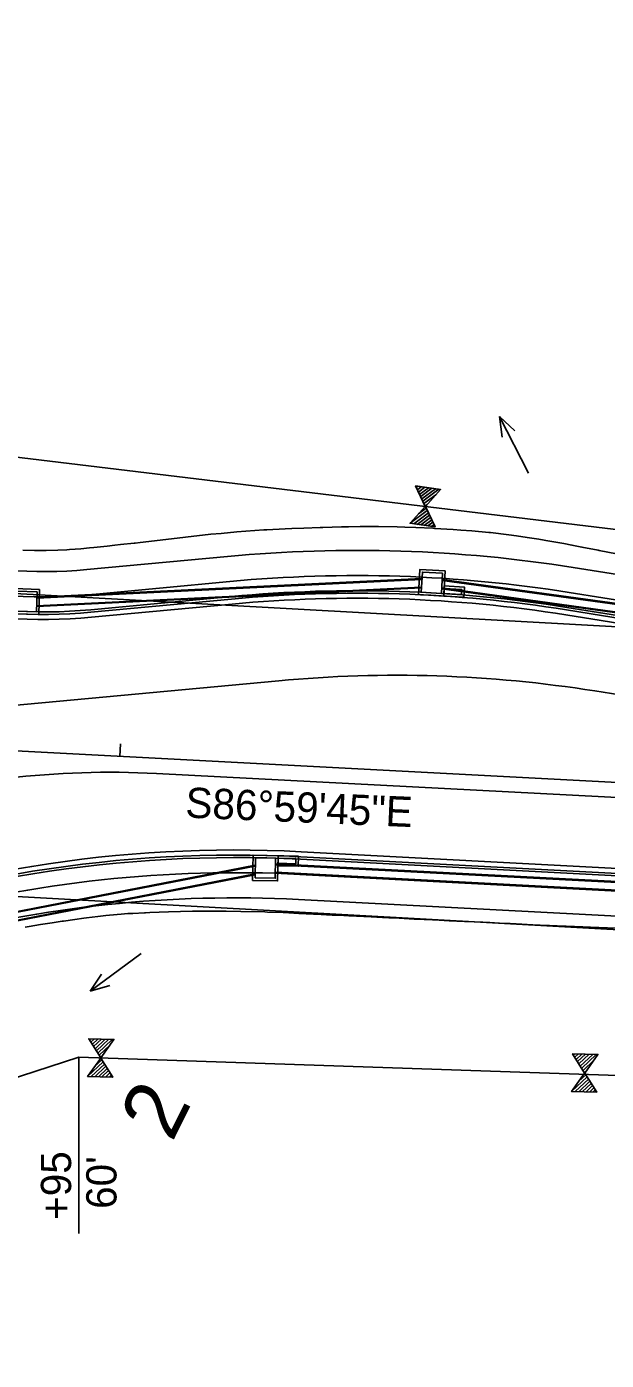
# Model space of a CAD drawing. Extents: x 670017 to 673226, y 705371 to 707498.
# Drawn here: x 671881.1 to 671996.1, y 706412.9 to 706677.4 of the extents above; entities that cross this region are included whole.
import ezdxf

# ---------------------------------------------------------------- set-up
doc = ezdxf.new("R2010")
doc.units = 0
for name, color, linetype in [('EL L 264', 7, 'Continuous'), ('EL R 264', 7, 'Continuous'), ('R_Drainage Flow Lines', 7, 'Continuous'), ('R_Drainage Stage 1', 7, 'Continuous'), ('R_Drainage Stage 2', 7, 'Continuous'), ('R_Fence', 7, 'Continuous'), ('R_Horz Alg', 7, 'Continuous'), ('R_Horz Alg Station', 7, 'Continuous'), ('R_Horz Alg Station Annot', 7, 'Continuous'), ('R_Horz Bearing', 7, 'Continuous'), ('R_No Plot', 7, 'Continuous'), ('R_No Plot FOC', 7, 'Continuous'), ('R_Proposed Const Limits', 7, 'Continuous'), ('R_Proposed Const Limits Stage 2', 7, 'Continuous'), ('R_Proposed Median', 7, 'Continuous'), ('R_Proposed Road', 7, 'Continuous'), ('R_Proposed Road Stage 2', 7, 'Continuous'), ('R_Proposed Sidewalk Stage 1', 7, 'Continuous'), ('R_Proposed Sidewalk Stage 2', 7, 'Continuous'), ('R_ROW', 7, 'Continuous'), ('R_ROW Annot', 7, 'Continuous'), ('R_Water Annot', 7, 'Continuous'), ('S_EXIST_ROW', 7, 'Continuous')]:
    doc.layers.add(name, color=color, linetype=linetype)

# ---------------------------------------------------------------- blocks, each defined once
blk = doc.blocks.new('FLOW ARROW')
at = {"layer": 'R_Water Annot'}
for p, q in [((-12.57, 0), (0, 0)), ((0, 0), (-3.85, 1.4)), ((0, 0), (-3.85, -1.4))]:
    blk.add_line(p, q, dxfattribs=at)

msp = doc.modelspace()

# ---------------------------------------------------------------- linework, layer by layer
at = {"layer": 'EL L 264'}
for p, q in [((671893.98, 706560.26), (671921.88, 706562.87)), ((671893.98, 706560.26), (671921.88, 706562.87)), ((671988.06, 706560.74), (672090.97, 706544.34)), ((671988.06, 706560.74), (672090.97, 706544.34))]:
    msp.add_line(p, q, dxfattribs=at)
for centre, radius, start, end in [((671884.56, 706660.82), 101, 237.03, 275.3546), ((671884.56, 706660.82), 101, 237.03, 275.3546), ((671946.51, 706300.03), 264, 80.9468, 95.3546), ((671946.51, 706300.03), 264, 80.9468, 95.3546)]:
    msp.add_arc(centre, radius, start, end, dxfattribs=at)
at = {"layer": 'EL R 264'}
msp.add_line((671935.55, 706513.76), (672188.31, 706500.5), dxfattribs=at)
msp.add_arc((671922.4, 706263.11), 251, 86.9958, 111.4581, dxfattribs=at)
at = {"layer": 'R_Drainage Stage 1'}
for p, q in [((671959.44, 706566.26), (671883.12, 706562.56)), ((671959.43, 706566.09), (671883.12, 706562.4)), ((671959.54, 706567.93), (671883.17, 706564.23)), ((671959.53, 706567.76), (671883.17, 706564.07)), ((672148.36, 706540.47), (671963.43, 706565.91)), ((672148.37, 706540.64), (671963.44, 706566.08)), ((672148.44, 706542.14), (671963.52, 706567.58)), ((672148.45, 706542.31), (671963.53, 706567.75))]:
    msp.add_line(p, q, dxfattribs=at)
for points in [[(671958.86, 706564.75), (671963.85, 706564.47), (671964.13, 706569.46), (671959.14, 706569.74)], [(671959.38, 706565.22), (671963.38, 706565), (671963.6, 706568.99), (671959.61, 706569.22)], [(671883.72, 706565.8), (671878.72, 706565.95), (671878.57, 706560.96), (671883.57, 706560.8)], [(671963.96, 706566.47), (671967.95, 706566.24), (671967.84, 706564.24), (671963.85, 706564.47)], [(671963.93, 706565.97), (671967.43, 706565.77), (671967.37, 706564.77), (671963.88, 706564.97)], [(671883.21, 706565.31), (671879.21, 706565.44), (671879.08, 706561.44), (671883.08, 706561.32)]]:
    msp.add_lwpolyline(points, close=True, dxfattribs=at)
at = {"layer": 'R_Drainage Stage 2'}
for p, q in [((671926.49, 706511.08), (671823.91, 706491.17)), ((671926.48, 706510.91), (671823.97, 706491.01)), ((672121.25, 706501.26), (671930.49, 706511.18)), ((672121.26, 706501.43), (671930.5, 706511.35)), ((671926.45, 706509.38), (671824.53, 706489.59)), ((671926.44, 706509.2), (671824.59, 706489.44)), ((672121.17, 706499.6), (671930.45, 706509.51)), ((672121.17, 706499.76), (671930.46, 706509.68))]:
    msp.add_line(p, q, dxfattribs=at)
for points in [[(671925.92, 706508.09), (671930.92, 706507.97), (671931.03, 706512.97), (671926.04, 706513.09)], [(671931.03, 706512.97), (671935.03, 706512.88), (671934.99, 706510.88), (671930.99, 706510.97)], [(671926.43, 706508.58), (671930.43, 706508.49), (671930.52, 706512.49), (671926.52, 706512.58)], [(671931.02, 706512.47), (671934.52, 706512.39), (671934.5, 706511.39), (671931, 706511.47)]]:
    msp.add_lwpolyline(points, close=True, dxfattribs=at)
at = {"layer": 'R_Fence'}
for p, q in [((671958.7, 706586.25), (671958.4, 706586.02)), ((671959.4, 706586.14), (671958.62, 706585.56)), ((671960.1, 706586.04), (671958.84, 706585.1)), ((671960.8, 706585.94), (671959.06, 706584.64)), ((671961.5, 706585.84), (671959.28, 706584.18)), ((671962.2, 706585.74), (671959.5, 706583.72)), ((671962.9, 706585.64), (671959.72, 706583.26)), ((671962.28, 706584.55), (671959.94, 706582.8)), ((671960.38, 706581.88), (671958.87, 706580.75)), ((671960.57, 706582.65), (671960.16, 706582.34)), ((671960.6, 706581.42), (671957.2, 706578.89)), ((671960.81, 706580.96), (671957.9, 706578.78)), ((671961.03, 706580.5), (671958.6, 706578.68)), ((671961.25, 706580.04), (671959.3, 706578.58)), ((671961.47, 706579.58), (671960, 706578.48)), ((671961.69, 706579.12), (671960.7, 706578.38)), ((671961.91, 706578.66), (671961.4, 706578.28)), ((671962.13, 706578.2), (671962.1, 706578.18)), ((671893.89, 706476.67), (671893.62, 706476.41)), ((671894.6, 706476.65), (671893.89, 706475.98)), ((671895.31, 706476.63), (671894.16, 706475.55)), ((671896.01, 706476.61), (671894.43, 706475.12)), ((671896.72, 706476.59), (671894.7, 706474.68)), ((671897.43, 706476.57), (671894.97, 706474.25)), ((671898.13, 706476.54), (671895.24, 706473.82)), ((671897.64, 706475.39), (671895.51, 706473.39)), ((671896.16, 706473.31), (671895.78, 706472.95)), ((671989.86, 706473.68), (671989.59, 706473.42)), ((671990.57, 706473.66), (671989.86, 706472.99)), ((671991.27, 706473.64), (671990.13, 706472.56)), ((671991.98, 706473.62), (671990.4, 706472.13)), ((671992.69, 706473.6), (671990.67, 706471.7)), ((671993.4, 706473.58), (671990.94, 706471.26)), ((671994.1, 706473.56), (671991.21, 706470.83)), ((671896.32, 706472.09), (671893.24, 706469.19)), ((671896.59, 706471.66), (671893.95, 706469.17)), ((671896.86, 706471.22), (671894.66, 706469.14)), ((671896.05, 706472.52), (671894.68, 706471.23)), ((671897.13, 706470.79), (671895.36, 706469.12)), ((671993.6, 706472.4), (671991.48, 706470.4)), ((671897.4, 706470.36), (671896.07, 706469.1)), ((671897.67, 706469.93), (671896.78, 706469.08)), ((671897.94, 706469.49), (671897.48, 706469.06)), ((671898.21, 706469.06), (671898.19, 706469.04)), ((671992.29, 706469.1), (671989.21, 706466.2)), ((671992.56, 706468.67), (671989.92, 706466.18)), ((671992.83, 706468.24), (671990.62, 706466.16)), ((671992.02, 706469.53), (671990.65, 706468.24)), ((671992.13, 706470.32), (671991.75, 706469.97)), ((671993.1, 706467.8), (671991.33, 706466.13)), ((671993.37, 706467.37), (671992.04, 706466.11)), ((671993.64, 706466.94), (671992.74, 706466.09)), ((671993.91, 706466.51), (671993.45, 706466.07)), ((671994.18, 706466.07), (671994.16, 706466.05))]:
    msp.add_line(p, q, dxfattribs=at)
for points in [[(671960.21, 706582.23), (671960.21, 706582.25), (671963.22, 706585.59), (671958.27, 706586.31), (671960.2, 706582.25), (671960.2, 706582.23), (671957.19, 706578.89), (671962.14, 706578.17), (671960.21, 706582.23)], [(671895.85, 706472.85), (671895.85, 706472.87), (671898.45, 706476.53), (671893.45, 706476.68), (671895.84, 706472.87), (671895.84, 706472.85), (671893.23, 706469.19), (671898.23, 706469.04), (671895.85, 706472.85)], [(671991.81, 706469.86), (671991.81, 706469.88), (671994.42, 706473.55), (671989.42, 706473.69), (671991.8, 706469.88), (671991.8, 706469.87), (671989.2, 706466.2), (671994.2, 706466.05), (671991.81, 706469.86)]]:
    msp.add_lwpolyline(points, dxfattribs=at)
at = {"layer": 'R_Horz Alg'}
msp.add_line((670501.52, 706606.05), (672734.79, 706488.84), dxfattribs=at)
at = {"layer": 'R_Horz Alg Station'}
msp.add_lwpolyline([(671899.73, 706535.17), (671899.6, 706532.67)], dxfattribs=at)
at = {"layer": 'R_No Plot'}
msp.add_lwpolyline([(672600.73, 706535.93), (672600.73, 706535.93), (672146.36, 706559.78), (671852.81, 706595.21), (671791.92, 706679.49), (671797.39, 707089.58)], dxfattribs=at)
at = {"layer": 'R_No Plot FOC'}
for p, q in [((671893.89, 706561.25), (671921.78, 706563.87)), ((672091.13, 706545.33), (671988.21, 706561.72)), ((672187.85, 706499.52), (671935.5, 706512.76))]:
    msp.add_line(p, q, dxfattribs=at)
for centre, radius, start, end in [((671884.56, 706660.82), 100, 237.03, 275.3546), ((671946.51, 706300.03), 265, 80.9468, 95.3546), ((671922.4, 706263.11), 250, 86.9958, 111.4581)]:
    msp.add_arc(centre, radius, start, end, dxfattribs=at)
at = {"layer": 'R_Proposed Const Limits'}
msp.add_lwpolyline([(671880.37, 706573.58), (671882.68, 706573.48), (671884.73, 706573.48), (671885, 706573.48), (671887.3, 706573.55), (671889.11, 706573.64), (671889.61, 706573.67), (671891.91, 706573.86), (671893.58, 706574.03), (671894.45, 706574.12), (671897.11, 706574.39), (671898.6, 706574.54), (671899.78, 706574.66), (671902.45, 706574.94), (671902.63, 706574.96), (671903.63, 706575.08), (671907.65, 706575.56), (671912.67, 706576.15), (671917.69, 706576.71), (671919.7, 706576.9), (671922.84, 706577.18), (671928.15, 706577.57), (671928.74, 706577.61), (671932.44, 706577.8), (671933.74, 706577.85), (671936.14, 706577.94), (671939.36, 706578.05), (671939.85, 706578.07), (671943.55, 706578.18), (671944.96, 706578.21), (671947.25, 706578.24), (671950.55, 706578.25), (671950.95, 706578.24), (671954.65, 706578.2), (671956.12, 706578.15), (671958.35, 706578.07), (671961.69, 706577.91), (671962.05, 706577.89), (671965.74, 706577.67), (671967.25, 706577.56), (671969.42, 706577.39), (671972.79, 706577.09), (671973.1, 706577.06), (671976.74, 706576.64), (671976.77, 706576.63), (671978.31, 706576.41), (671980.42, 706576.09), (671982.73, 706575.72), (671983.8, 706575.55), (671984.07, 706575.5), (671987.7, 706574.86), (671989.27, 706574.57), (671991.26, 706574.19), (671994.5, 706573.57), (671994.69, 706573.53), (671998.13, 706572.86)], dxfattribs=at)
at = {"layer": 'R_Proposed Const Limits Stage 2'}
msp.add_lwpolyline([(671880.83, 706498.82), (671881.66, 706498.96), (671883.88, 706499.33), (671883.92, 706499.33), (671886.18, 706499.68), (671888.19, 706499.97), (671888.45, 706500.01), (671890.72, 706500.32), (671892.5, 706500.57), (671893, 706500.64), (671895.29, 706500.92), (671896.83, 706501.1), (671897.58, 706501.18), (671899.89, 706501.4), (671901.18, 706501.48), (671902.2, 706501.54), (671904.52, 706501.65), (671904.68, 706501.66), (671905.56, 706501.7), (671909.27, 706501.85), (671914.05, 706501.97), (671918.83, 706501.99), (671920.74, 706501.97), (671923.6, 706501.93), (671928.35, 706501.82), (671928.88, 706501.8), (671932.01, 706501.68), (671933.11, 706501.63), (671935.15, 706501.54), (671938.01, 706501.39), (671938.45, 706501.37), (671941.75, 706501.21), (671943, 706501.15), (671945.05, 706501.05), (671948, 706500.91), (671948.36, 706500.89), (671951.68, 706500.73), (671952.99, 706500.66), (671954.99, 706500.57), (671957.99, 706500.42), (671958.31, 706500.41), (671961.62, 706500.25), (671962.98, 706500.18), (671964.94, 706500.09), (671967.97, 706499.94), (671968.26, 706499.93), (671971.54, 706499.77), (671971.58, 706499.77), (671972.97, 706499.7), (671974.89, 706499.61), (671977, 706499.51), (671977.96, 706499.46), (671978.21, 706499.45), (671981.52, 706499.29), (671982.96, 706499.22), (671984.83, 706499.13), (671987.95, 706498.99), (671988.14, 706498.98), (671991.44, 706498.86), (671992.95, 706498.8), (671997.95, 706498.61)], dxfattribs=at)
at = {"layer": 'R_Proposed Median'}
for p, q in [((671877.73, 706542.67), (671931.12, 706547.67)), ((672088.77, 706530.51), (671993.79, 706545.65)), ((672189.04, 706514.48), (671906.9, 706529.28))]:
    msp.add_line(p, q, dxfattribs=at)
for centre, radius, start, end in [((671954.45, 706298.76), 250, 80.9468, 95.3546), ((671897.73, 706354.52), 175, 86.9958, 106.4093)]:
    msp.add_arc(centre, radius, start, end, dxfattribs=at)
at = {"layer": 'R_Proposed Road'}
for p, q in [((671893.84, 706561.75), (671921.74, 706564.37)), ((671893.98, 706560.26), (671921.88, 706562.87)), ((672090.97, 706544.34), (671988.06, 706560.74)), ((672091.21, 706545.82), (671988.29, 706562.22))]:
    msp.add_line(p, q, dxfattribs=at)
for centre, radius, start, end in [((671884.56, 706660.82), 99.5, 237.03, 275.3546), ((671884.56, 706660.82), 101, 237.03, 275.3546), ((671946.51, 706300.03), 265.5, 80.9468, 95.3546), ((671946.51, 706300.03), 264, 80.9468, 95.3546)]:
    msp.add_arc(centre, radius, start, end, dxfattribs=at)
at = {"layer": 'R_Proposed Road Stage 2'}
for p, q in [((672188.31, 706500.5), (671935.55, 706513.76)), ((672188.23, 706499), (671935.47, 706512.26))]:
    msp.add_line(p, q, dxfattribs=at)
for radius in [251, 249.5]:
    msp.add_arc((671922.4, 706263.11), radius, 86.9958, 111.4581, dxfattribs=at)
at = {"layer": 'R_Proposed Sidewalk Stage 1'}
for p, q in [((671893.1, 706569.72), (671920.99, 706572.33)), ((672093.51, 706553.55), (671989.55, 706570.12)), ((671893.56, 706564.74), (671921.46, 706567.35)), ((672092.72, 706548.62), (671988.76, 706565.18))]:
    msp.add_line(p, q, dxfattribs=at)
for centre, radius, start, end in [((671884.56, 706660.82), 91.5, 255.4612, 275.3546), ((671946.51, 706300.03), 273.5, 80.9468, 95.3546), ((671946.51, 706300.03), 268.5, 80.9468, 95.3546), ((671884.56, 706660.82), 96.5, 254.5309, 275.3546)]:
    msp.add_arc(centre, radius, start, end, dxfattribs=at)
at = {"layer": 'R_Proposed Sidewalk Stage 2'}
for p, q in [((672187.68, 706496.02), (671935.32, 706509.27)), ((672187.45, 706491.03), (671935.05, 706504.27))]:
    msp.add_line(p, q, dxfattribs=at)
for radius, end in [(246.5, 105.3152), (241.5, 104.9768)]:
    msp.add_arc((671922.4, 706263.11), radius, 86.9958, end, dxfattribs=at)
at = {"layer": 'R_ROW'}
for points in [[(672600.73, 706535.93), (672600.73, 706535.93), (672146.36, 706559.78), (671852.81, 706595.21), (671791.92, 706679.49), (671797.39, 707089.58)], [(672596.28, 706451.05), (672596.28, 706451.05), (672161.7, 706463.84), (671891.46, 706473.02), (671825.24, 706451.46), (671776.29, 706399.8), (671754.1, 706085.43), (671832.11, 706032.37), (671817.47, 705912.84), (671726.19, 705881.35)]]:
    msp.add_lwpolyline(points, dxfattribs=at)
at = {"layer": 'R_ROW Annot'}
msp.add_lwpolyline([(671891.46, 706473.02), (671891.46, 706458.02), (671891.46, 706438.02)], dxfattribs=at)
at = {"layer": 'S_EXIST_ROW'}
for points in [[(670020.59, 706668.53), (670619.99, 706639.58), (670619.86, 706634.58), (671728.16, 706573.3), (673225.88, 706490.48)], [(670017.21, 706598.61), (670616.41, 706569.67), (670616.54, 706574.67), (671724.85, 706513.39), (673222.56, 706430.57)]]:
    msp.add_lwpolyline(points, dxfattribs=at)

# ---------------------------------------------------------------- block references
at = {"layer": 'R_Drainage Flow Lines'}
for p, rotation in [((671974.92, 706600.05), 117.15978551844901), ((671893.73, 706486.09), -143.41342062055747)]:
    msp.add_blockref('FLOW ARROW', p, dxfattribs=dict(at, rotation=rotation))

# ---------------------------------------------------------------- texts
at = {"layer": 'R_Horz Alg Station Annot'}
msp.add_text('2', height=12, rotation=63.6607, dxfattribs=at).set_placement((671909.98, 706455.98))
at = {"layer": 'R_Horz Bearing'}
msp.add_text('S86%%d59\'45"E', height=6, rotation=357.5741, dxfattribs=at).set_placement((671912.54, 706520.55))
at = {"layer": 'R_ROW Annot'}
for s, p in [('+95', (671889.96, 706440.75)), ("60'", (671898.96, 706442.93))]:
    msp.add_text(s, height=6, rotation=90, dxfattribs=at).set_placement(p)

doc.saveas('drawing.dxf')
